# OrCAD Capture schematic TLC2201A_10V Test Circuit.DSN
size A; title: TLC220x, TLC220xA, TLC220xB, TLC220xY Advanced LinCMOS; rev: 1.0; note: Datasheet: SLOS175B EVM: N/A
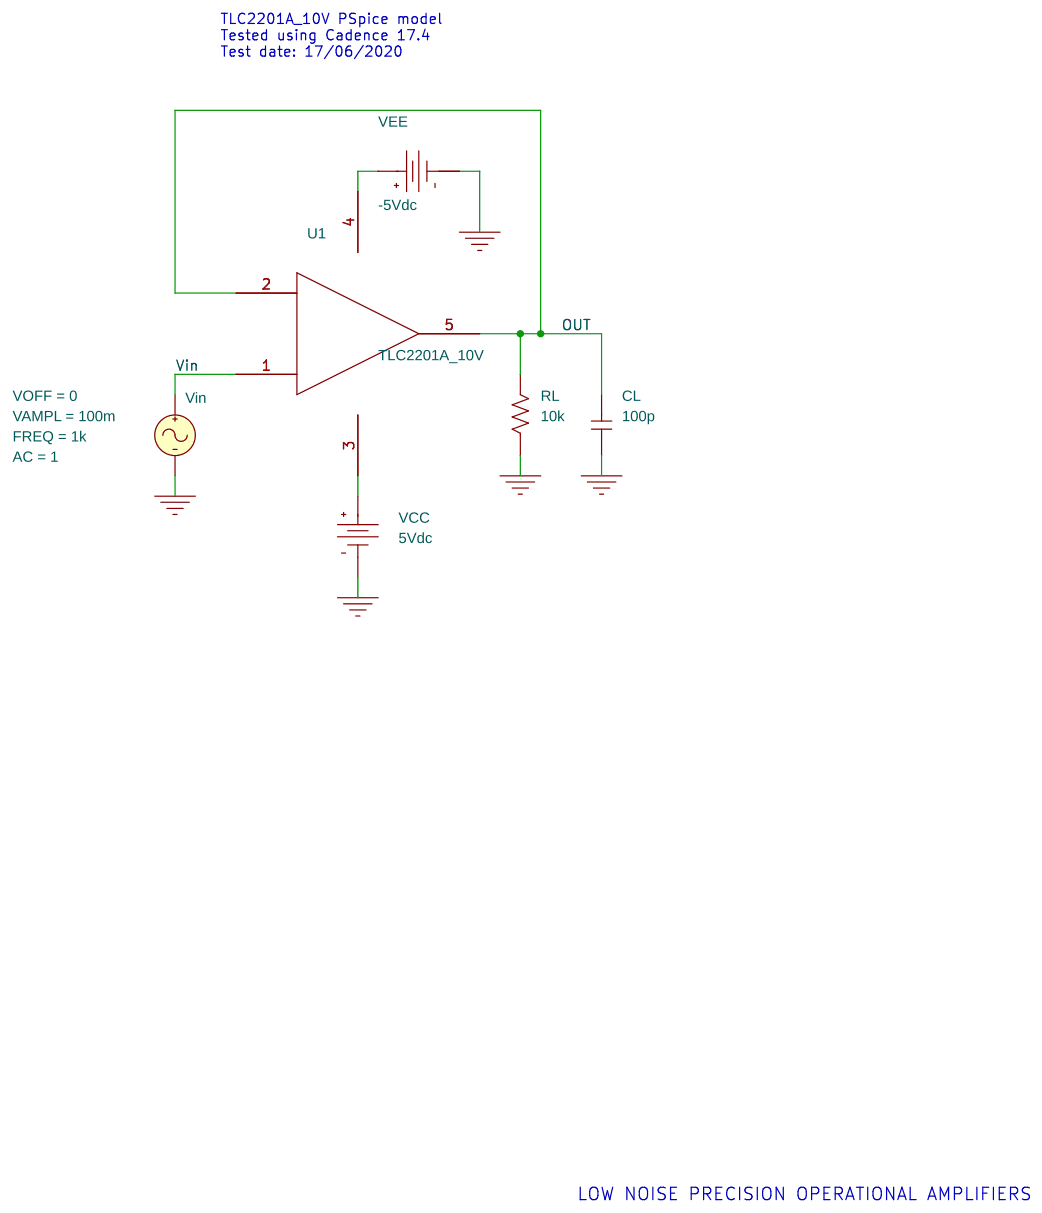
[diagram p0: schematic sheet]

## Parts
CL  100p  [RAD/CK05]
RL  10k  [AX/RC05]
U1  TLC2201A_10V
VCC  VDC
VEE  VDC
Vin  VSIN

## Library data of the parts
CL = C
RL = R
U1 = TLC2201A_10V
VCC = VDC: DC: 5Vdc
VEE = VDC: DC: -5Vdc
Vin = VSIN: AC: 1; FREQ: 1k; VAMPL: 100m; VOFF: 0

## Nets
Vin: U1.1(IN+) Vin.1(+)
0: CL.1 RL.1 VCC.1(-) VEE.1(-) Vin.2(-)
OUT: CL.2 RL.2 U1.2(IN-) U1.5(OUT)
N22995: U1.4(VEE) VEE.0(+)
N23017: U1.3(VCC) VCC.0(+)

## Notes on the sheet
- TLC2201A_10V PSpice model
  Tested using Cadence 17.4
  Test date: 17/06/2020
- LOW NOISE PRECISION OPERATIONAL AMPLIFIERS
